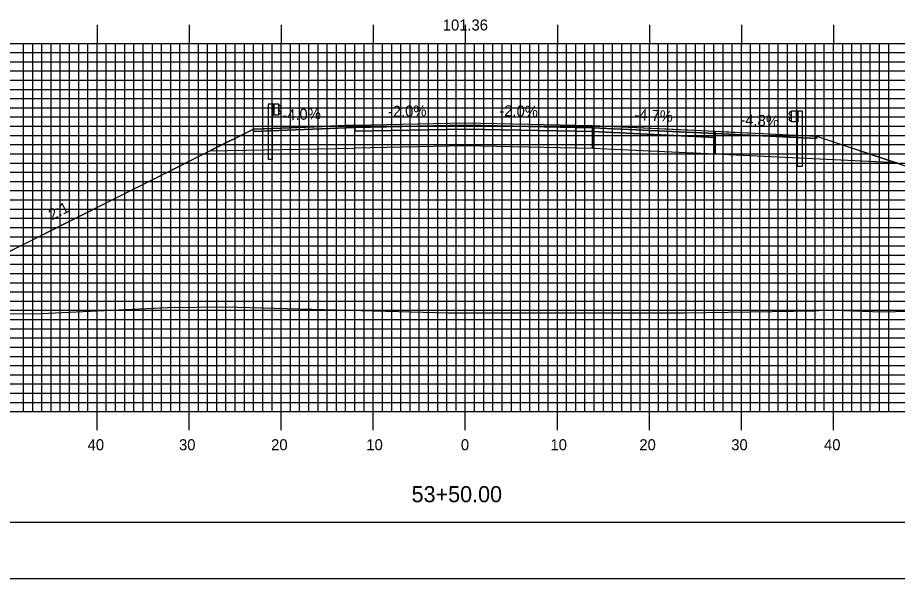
# Model space of a CAD drawing. Extents: x 1756282 to 1756625, y 442591 to 442811.
# Drawn here: x 1756398.9 to 1756494.5, y 442590.5 to 442651.5 of the extents above; entities that cross this region are included whole.
import ezdxf

# ---------------------------------------------------------------- set-up
doc = ezdxf.new("R2010")
doc.units = 0
for name, color, linetype in [('ANNOTATION', 7, 'Continuous'), ('BORDER', 7, 'Continuous'), ('D_Guardrail_Beam_Lt', 7, 'Continuous'), ('D_Guardrail_Beam_Rt', 7, 'Continuous'), ('D_Roadway_Centerline', 7, 'Continuous'), ('D_Roadway_Centerline_Text', 7, 'Continuous'), ('D_Roadway_Edge_Shoulder', 7, 'Continuous'), ('D_Roadway_Edge_TW', 7, 'Continuous'), ('D_Roadway_Pavement', 7, 'Continuous'), ('D_Roadway_SlopeLines', 7, 'Continuous'), ('D_Roadway_SubGrade', 7, 'Continuous'), ('H_V ANNOTATION', 7, 'Continuous'), ('MAJOR', 7, 'Continuous'), ('MINOR', 7, 'Continuous'), ('PLOT BOUNDARY', 7, 'Continuous'), ('S_Roadway_Centerline', 7, 'Continuous')]:
    doc.layers.add(name, color=color, linetype=linetype)

msp = doc.modelspace()

# ---------------------------------------------------------------- linework, layer by layer
at = {"layer": 'BORDER'}
msp.add_lwpolyline([(1756297.97, 442596.665), (1756617.97, 442596.665), (1756617.97, 442806.665), (1756297.97, 442806.665)], close=True, dxfattribs=at)
at = {"layer": 'D_Guardrail_Beam_Lt'}
for p, q in [((1756426.141, 442642.051), (1756426.141, 442636.051)), ((1756426.611, 442642.051), (1756426.141, 442642.051)), ((1756427.299, 442642.051), (1756426.611, 442642.051)), ((1756426.611, 442642.051), (1756426.611, 442640.885)), ((1756426.674, 442642.051), (1756426.674, 442640.885)), ((1756426.778, 442642.051), (1756426.778, 442640.885)), ((1756427.299, 442640.885), (1756427.299, 442642.051)), ((1756427.299, 442641.968), (1756427.373, 442641.953)), ((1756427.389, 442641.947), (1756427.532, 442641.847)), ((1756427.303, 442641.503), (1756427.303, 442641.433)), ((1756427.532, 442641.704), (1756427.337, 442641.567)), ((1756427.337, 442641.368), (1756427.532, 442641.232)), ((1756427.532, 442641.089), (1756427.389, 442640.989)), ((1756426.611, 442640.885), (1756427.299, 442640.885)), ((1756426.632, 442636.051), (1756426.632, 442640.885)), ((1756427.373, 442640.982), (1756427.299, 442640.968)), ((1756426.632, 442636.051), (1756426.141, 442636.051))]:
    msp.add_line(p, q, dxfattribs=at)
for centre, major_axis, start_param, end_param in [((1756427.365, 442641.913), (0.0417, 0), 0.959931, 1.376053), ((1756427.382, 442641.503), (-0.0789, 0), 5.323254, 6.283185), ((1756427.382, 442641.433), (-0.0789, 0), 6.283185, 7.243116), ((1756427.365, 442641.023), (0.0417, 0), 4.907132, 5.323254), ((1756427.482, 442641.775), (0.0877, 0), 5.323254, 7.243116), ((1756427.482, 442641.161), (0.0877, 0), 5.323254, 7.243116)]:
    msp.add_ellipse(centre, major_axis=major_axis, ratio=0.995501, start_param=start_param, end_param=end_param, dxfattribs=at)
at = {"layer": 'D_Guardrail_Beam_Rt'}
for p, q in [((1756482.908, 442641.213), (1756482.765, 442641.113)), ((1756482.998, 442641.234), (1756482.924, 442641.219)), ((1756482.998, 442641.317), (1756483.686, 442641.317)), ((1756482.998, 442640.151), (1756482.998, 442641.317)), ((1756483.519, 442641.317), (1756483.519, 442640.151)), ((1756483.623, 442641.317), (1756483.623, 442640.151)), ((1756483.686, 442641.317), (1756484.157, 442641.317)), ((1756483.686, 442641.317), (1756483.686, 442640.151)), ((1756484.157, 442641.317), (1756484.157, 442635.317)), ((1756482.765, 442640.97), (1756482.96, 442640.834)), ((1756482.96, 442640.635), (1756482.765, 442640.498)), ((1756482.765, 442640.355), (1756482.908, 442640.255)), ((1756482.924, 442640.249), (1756482.998, 442640.234)), ((1756482.994, 442640.769), (1756482.994, 442640.699)), ((1756483.686, 442640.151), (1756482.998, 442640.151)), ((1756483.665, 442635.317), (1756483.665, 442640.151)), ((1756483.665, 442635.317), (1756484.157, 442635.317))]:
    msp.add_line(p, q, dxfattribs=at)
for centre, major_axis, start_param, end_param in [((1756482.815, 442641.041), (-0.0877, 0), 5.323254, 7.243116), ((1756482.932, 442641.179), (-0.0417, 0), 4.907132, 5.323254), ((1756482.815, 442640.427), (-0.0877, 0), 5.323254, 7.243116), ((1756482.932, 442640.289), (-0.0417, 0), 0.959931, 1.376053), ((1756482.915, 442640.769), (0.0789, 0), 0, 0.959931), ((1756482.915, 442640.699), (0.0789, 0), 5.323254, 6.283185)]:
    msp.add_ellipse(centre, major_axis=major_axis, ratio=0.995501, start_param=start_param, end_param=end_param, dxfattribs=at)
at = {"layer": 'D_Roadway_Centerline'}
msp.add_lwpolyline([(1756394.319, 442624.223), (1756419.82, 442636.973), (1756424.57, 442639.348), (1756427.57, 442639.468), (1756435.57, 442639.788), (1756447.57, 442640.028), (1756459.57, 442639.788), (1756461.374, 442639.752), (1756469.438, 442639.369), (1756474.711, 442639.119), (1756476.511, 442639.032), (1756479.925, 442638.868), (1756482.728, 442638.734), (1756483.42, 442638.701), (1756485.734, 442638.59), (1756493.684, 442635.929), (1756494.453, 442635.671), (1756495.01, 442635.485)], dxfattribs=at)
at = {"layer": 'D_Roadway_Edge_Shoulder'}
for points in [[(1756435.57, 442639.788), (1756427.57, 442639.468), (1756427.57, 442639.468), (1756424.57, 442639.348), (1756424.57, 442639.098), (1756435.57, 442639.538)], [(1756474.711, 442639.119), (1756482.728, 442638.734), (1756482.728, 442638.734), (1756485.734, 442638.59), (1756485.734, 442638.34), (1756474.711, 442638.869)]]:
    msp.add_lwpolyline(points, close=True, dxfattribs=at)
at = {"layer": 'D_Roadway_Edge_TW'}
for points in [[(1756435.57, 442639.538), (1756435.57, 442639.788), (1756447.57, 442640.028), (1756459.57, 442639.788), (1756459.57, 442639.538), (1756447.57, 442639.778)], [(1756459.57, 442639.788), (1756461.374, 442639.752), (1756461.374, 442639.502), (1756459.57, 442639.538)], [(1756461.374, 442639.752), (1756474.711, 442639.119), (1756474.711, 442638.869), (1756461.374, 442639.502)]]:
    msp.add_lwpolyline(points, close=True, dxfattribs=at)
at = {"layer": 'D_Roadway_Pavement'}
for points in [[(1756435.57, 442639.121), (1756435.57, 442639.538), (1756447.57, 442639.778), (1756459.57, 442639.538), (1756459.57, 442639.121), (1756447.57, 442639.361)], [(1756459.57, 442639.538), (1756461.374, 442639.502), (1756461.374, 442639.085), (1756459.57, 442639.121)], [(1756461.374, 442639.502), (1756474.711, 442638.869), (1756474.711, 442638.452), (1756461.374, 442639.085)]]:
    msp.add_lwpolyline(points, close=True, dxfattribs=at)
for points in [[(1756435.57, 442639.538), (1756435.57, 442639.121)], [(1756474.711, 442638.869), (1756474.711, 442638.452)], [(1756474.711, 442638.869), (1756474.711, 442638.452)]]:
    msp.add_lwpolyline(points, dxfattribs=at)
at = {"layer": 'D_Roadway_SlopeLines'}
for points in [[(1756424.57, 442639.348), (1756394.322, 442624.224)], [(1756485.734, 442638.59), (1756541.116, 442620.049)]]:
    msp.add_lwpolyline(points, dxfattribs=at)
at = {"layer": 'D_Roadway_SubGrade'}
for points in [[(1756435.57, 442639.121), (1756435.57, 442639.538), (1756424.57, 442639.098), (1756424.57, 442639.348), (1756419.82, 442636.973), (1756435.57, 442637.288)], [(1756435.57, 442637.288), (1756435.57, 442639.121), (1756447.57, 442639.361), (1756459.57, 442639.121), (1756459.57, 442637.288), (1756447.57, 442637.528)], [(1756459.57, 442639.121), (1756461.374, 442639.085), (1756461.374, 442637.252), (1756459.57, 442637.288)], [(1756461.374, 442639.085), (1756474.711, 442638.452), (1756474.711, 442636.619), (1756461.374, 442637.252)], [(1756474.711, 442638.452), (1756474.711, 442638.869), (1756485.734, 442638.34), (1756485.734, 442638.59), (1756494.453, 442635.671), (1756474.711, 442636.619)]]:
    msp.add_lwpolyline(points, close=True, dxfattribs=at)
at = {"layer": 'MAJOR'}
for p, q in [((1756407.57, 442650.669), (1756407.57, 442648.665)), ((1756417.57, 442650.669), (1756417.57, 442648.665)), ((1756427.57, 442650.669), (1756427.57, 442648.665)), ((1756437.57, 442650.669), (1756437.57, 442648.665)), ((1756447.57, 442650.669), (1756447.57, 442648.665)), ((1756457.57, 442650.669), (1756457.57, 442648.665)), ((1756467.57, 442650.669), (1756467.57, 442648.665)), ((1756477.57, 442650.669), (1756477.57, 442648.665)), ((1756487.57, 442650.669), (1756487.57, 442648.665)), ((1756307.57, 442648.665), (1756587.57, 442648.665)), ((1756307.57, 442648.665), (1756587.57, 442648.665)), ((1756407.57, 442608.665), (1756407.57, 442648.665)), ((1756417.57, 442608.665), (1756417.57, 442648.665)), ((1756427.57, 442608.665), (1756427.57, 442648.665)), ((1756437.57, 442608.665), (1756437.57, 442648.665)), ((1756447.57, 442608.665), (1756447.57, 442648.665)), ((1756457.57, 442608.665), (1756457.57, 442648.665)), ((1756467.57, 442608.665), (1756467.57, 442648.665)), ((1756477.57, 442608.665), (1756477.57, 442648.665)), ((1756487.57, 442608.665), (1756487.57, 442648.665)), ((1756307.57, 442643.665), (1756587.57, 442643.665)), ((1756307.57, 442638.665), (1756587.57, 442638.665)), ((1756307.57, 442633.665), (1756587.57, 442633.665)), ((1756307.57, 442628.665), (1756587.57, 442628.665)), ((1756307.57, 442623.665), (1756587.57, 442623.665)), ((1756307.57, 442618.665), (1756587.57, 442618.665)), ((1756307.57, 442613.665), (1756587.57, 442613.665)), ((1756307.57, 442608.665), (1756587.57, 442608.665)), ((1756307.57, 442608.665), (1756587.57, 442608.665)), ((1756407.57, 442606.661), (1756407.57, 442608.665)), ((1756417.57, 442606.661), (1756417.57, 442608.665)), ((1756427.57, 442606.661), (1756427.57, 442608.665)), ((1756437.57, 442606.661), (1756437.57, 442608.665)), ((1756447.57, 442606.661), (1756447.57, 442608.665)), ((1756457.57, 442606.661), (1756457.57, 442608.665)), ((1756467.57, 442606.661), (1756467.57, 442608.665)), ((1756477.57, 442606.661), (1756477.57, 442608.665)), ((1756487.57, 442606.661), (1756487.57, 442608.665))]:
    msp.add_line(p, q, dxfattribs=at)
at = {"layer": 'MINOR'}
for p, q in [((1756399.57, 442608.665), (1756399.57, 442648.665)), ((1756400.57, 442608.665), (1756400.57, 442648.665)), ((1756401.57, 442608.665), (1756401.57, 442648.665)), ((1756402.57, 442608.665), (1756402.57, 442648.665)), ((1756403.57, 442608.665), (1756403.57, 442648.665)), ((1756404.57, 442608.665), (1756404.57, 442648.665)), ((1756405.57, 442608.665), (1756405.57, 442648.665)), ((1756406.57, 442608.665), (1756406.57, 442648.665)), ((1756408.57, 442608.665), (1756408.57, 442648.665)), ((1756409.57, 442608.665), (1756409.57, 442648.665)), ((1756410.57, 442608.665), (1756410.57, 442648.665)), ((1756411.57, 442608.665), (1756411.57, 442648.665)), ((1756412.57, 442608.665), (1756412.57, 442648.665)), ((1756413.57, 442608.665), (1756413.57, 442648.665)), ((1756414.57, 442608.665), (1756414.57, 442648.665)), ((1756415.57, 442608.665), (1756415.57, 442648.665)), ((1756416.57, 442608.665), (1756416.57, 442648.665)), ((1756418.57, 442608.665), (1756418.57, 442648.665)), ((1756419.57, 442608.665), (1756419.57, 442648.665)), ((1756420.57, 442608.665), (1756420.57, 442648.665)), ((1756421.57, 442608.665), (1756421.57, 442648.665)), ((1756422.57, 442608.665), (1756422.57, 442648.665)), ((1756423.57, 442608.665), (1756423.57, 442648.665)), ((1756424.57, 442608.665), (1756424.57, 442648.665)), ((1756425.57, 442608.665), (1756425.57, 442648.665)), ((1756426.57, 442608.665), (1756426.57, 442648.665)), ((1756428.57, 442608.665), (1756428.57, 442648.665)), ((1756429.57, 442608.665), (1756429.57, 442648.665)), ((1756430.57, 442608.665), (1756430.57, 442648.665)), ((1756431.57, 442608.665), (1756431.57, 442648.665)), ((1756432.57, 442608.665), (1756432.57, 442648.665)), ((1756433.57, 442608.665), (1756433.57, 442648.665)), ((1756434.57, 442608.665), (1756434.57, 442648.665)), ((1756435.57, 442608.665), (1756435.57, 442648.665)), ((1756436.57, 442608.665), (1756436.57, 442648.665)), ((1756438.57, 442608.665), (1756438.57, 442648.665)), ((1756439.57, 442608.665), (1756439.57, 442648.665)), ((1756440.57, 442608.665), (1756440.57, 442648.665)), ((1756441.57, 442608.665), (1756441.57, 442648.665)), ((1756442.57, 442608.665), (1756442.57, 442648.665)), ((1756443.57, 442608.665), (1756443.57, 442648.665)), ((1756444.57, 442608.665), (1756444.57, 442648.665)), ((1756445.57, 442608.665), (1756445.57, 442648.665)), ((1756446.57, 442608.665), (1756446.57, 442648.665)), ((1756448.57, 442608.665), (1756448.57, 442648.665)), ((1756449.57, 442608.665), (1756449.57, 442648.665)), ((1756450.57, 442608.665), (1756450.57, 442648.665)), ((1756451.57, 442608.665), (1756451.57, 442648.665)), ((1756452.57, 442608.665), (1756452.57, 442648.665)), ((1756453.57, 442608.665), (1756453.57, 442648.665)), ((1756454.57, 442608.665), (1756454.57, 442648.665)), ((1756455.57, 442608.665), (1756455.57, 442648.665)), ((1756456.57, 442608.665), (1756456.57, 442648.665)), ((1756458.57, 442608.665), (1756458.57, 442648.665)), ((1756459.57, 442608.665), (1756459.57, 442648.665)), ((1756460.57, 442608.665), (1756460.57, 442648.665)), ((1756461.57, 442608.665), (1756461.57, 442648.665)), ((1756462.57, 442608.665), (1756462.57, 442648.665)), ((1756463.57, 442608.665), (1756463.57, 442648.665)), ((1756464.57, 442608.665), (1756464.57, 442648.665)), ((1756465.57, 442608.665), (1756465.57, 442648.665)), ((1756466.57, 442608.665), (1756466.57, 442648.665)), ((1756468.57, 442608.665), (1756468.57, 442648.665)), ((1756469.57, 442608.665), (1756469.57, 442648.665)), ((1756470.57, 442608.665), (1756470.57, 442648.665)), ((1756471.57, 442608.665), (1756471.57, 442648.665)), ((1756472.57, 442608.665), (1756472.57, 442648.665)), ((1756473.57, 442608.665), (1756473.57, 442648.665)), ((1756474.57, 442608.665), (1756474.57, 442648.665)), ((1756475.57, 442608.665), (1756475.57, 442648.665)), ((1756476.57, 442608.665), (1756476.57, 442648.665)), ((1756478.57, 442608.665), (1756478.57, 442648.665)), ((1756479.57, 442608.665), (1756479.57, 442648.665)), ((1756480.57, 442608.665), (1756480.57, 442648.665)), ((1756481.57, 442608.665), (1756481.57, 442648.665)), ((1756482.57, 442608.665), (1756482.57, 442648.665)), ((1756483.57, 442608.665), (1756483.57, 442648.665)), ((1756484.57, 442608.665), (1756484.57, 442648.665)), ((1756485.57, 442608.665), (1756485.57, 442648.665)), ((1756486.57, 442608.665), (1756486.57, 442648.665)), ((1756488.57, 442608.665), (1756488.57, 442648.665)), ((1756489.57, 442608.665), (1756489.57, 442648.665)), ((1756490.57, 442608.665), (1756490.57, 442648.665)), ((1756491.57, 442608.665), (1756491.57, 442648.665)), ((1756492.57, 442608.665), (1756492.57, 442648.665)), ((1756493.57, 442608.665), (1756493.57, 442648.665)), ((1756307.57, 442647.665), (1756587.57, 442647.665)), ((1756307.57, 442646.665), (1756587.57, 442646.665)), ((1756307.57, 442645.665), (1756587.57, 442645.665)), ((1756307.57, 442644.665), (1756587.57, 442644.665)), ((1756307.57, 442642.665), (1756587.57, 442642.665)), ((1756307.57, 442641.665), (1756587.57, 442641.665)), ((1756307.57, 442640.665), (1756587.57, 442640.665)), ((1756307.57, 442639.665), (1756587.57, 442639.665)), ((1756307.57, 442637.665), (1756587.57, 442637.665)), ((1756307.57, 442636.665), (1756587.57, 442636.665)), ((1756307.57, 442635.665), (1756587.57, 442635.665)), ((1756307.57, 442634.665), (1756587.57, 442634.665)), ((1756307.57, 442632.665), (1756587.57, 442632.665)), ((1756307.57, 442631.665), (1756587.57, 442631.665)), ((1756307.57, 442630.665), (1756587.57, 442630.665)), ((1756307.57, 442629.665), (1756587.57, 442629.665)), ((1756307.57, 442627.665), (1756587.57, 442627.665)), ((1756307.57, 442626.665), (1756587.57, 442626.665)), ((1756307.57, 442625.665), (1756587.57, 442625.665)), ((1756307.57, 442624.665), (1756587.57, 442624.665)), ((1756307.57, 442622.665), (1756587.57, 442622.665)), ((1756307.57, 442621.665), (1756587.57, 442621.665)), ((1756307.57, 442620.665), (1756587.57, 442620.665)), ((1756307.57, 442619.665), (1756587.57, 442619.665)), ((1756307.57, 442617.665), (1756587.57, 442617.665)), ((1756307.57, 442616.665), (1756587.57, 442616.665)), ((1756307.57, 442615.665), (1756587.57, 442615.665)), ((1756307.57, 442614.665), (1756587.57, 442614.665)), ((1756307.57, 442612.665), (1756587.57, 442612.665)), ((1756307.57, 442611.665), (1756587.57, 442611.665)), ((1756307.57, 442610.665), (1756587.57, 442610.665)), ((1756307.57, 442609.665), (1756587.57, 442609.665))]:
    msp.add_line(p, q, dxfattribs=at)
at = {"layer": 'PLOT BOUNDARY'}
msp.add_lwpolyline([(1756281.783, 442590.547), (1756621.783, 442590.547), (1756621.783, 442810.547), (1756281.783, 442810.547)], close=True, dxfattribs=at)
at = {"layer": 'S_Roadway_Centerline'}
msp.add_lwpolyline([(1756307.57, 442618.076), (1756314.44, 442618.161), (1756314.669, 442617.912), (1756326.373, 442617.543), (1756331.277, 442617.486), (1756351.519, 442618.675), (1756360.562, 442619.108), (1756369.53, 442619.264), (1756401.492, 442619.32), (1756415.224, 442619.955), (1756421.47, 442620.052), (1756445.661, 442619.395), (1756471.396, 442619.404), (1756485.635, 442619.606), (1756486.605, 442619.72), (1756492.846, 442619.489), (1756514.562, 442620.043), (1756517.589, 442619.607), (1756534.909, 442619.984), (1756554.069, 442620.185), (1756568.955, 442620.313), (1756579.695, 442620.361), (1756585.039, 442620.349), (1756587.57, 442620.186)], dxfattribs=at)

# ---------------------------------------------------------------- texts
at = {"layer": 'ANNOTATION'}
for s, rotation, p in [('-2.0%', 358.85424, (1756451.256, 442640.755)), ('-4.0%', 2.29061, (1756427.702, 442640.275)), ('-2.0%', 1.14576, (1756439.176, 442640.66)), ('-4.7%', 357.28192, (1756465.903, 442640.339)), ('-4.8%', 357.25267, (1756477.428, 442639.791)), ('2:1', 26.56505, (1756402.657, 442629.428))]:
    msp.add_text(s, height=1.2, rotation=rotation, dxfattribs=at).set_placement(p)
at = {"layer": 'D_Roadway_Centerline'}
for s, p in [('C', (1756447.565, 442640.028)), ('L', (1756447.57, 442640.021))]:
    msp.add_text(s, height=0.0146, dxfattribs=at).set_placement(p)
at = {"layer": 'D_Roadway_Centerline_Text'}
msp.add_text('101.36', height=1.2, dxfattribs=at).set_placement((1756445.119, 442650.058))
at = {"layer": 'H_V ANNOTATION'}
for s, height, p in [('40', 1.2, (1756406.542, 442604.465)), ('30', 1.2, (1756416.467, 442604.465)), ('20', 1.2, (1756426.478, 442604.465)), ('10', 1.2, (1756436.821, 442604.465)), ('0', 1.2, (1756447.088, 442604.465)), ('10', 1.2, (1756456.821, 442604.465)), ('20', 1.2, (1756466.478, 442604.465)), ('30', 1.2, (1756476.467, 442604.465)), ('40', 1.2, (1756486.542, 442604.465)), ('53+50.00', 1.75, (1756441.733, 442598.821))]:
    msp.add_text(s, height=height, dxfattribs=at).set_placement(p)

doc.saveas('drawing.dxf')
